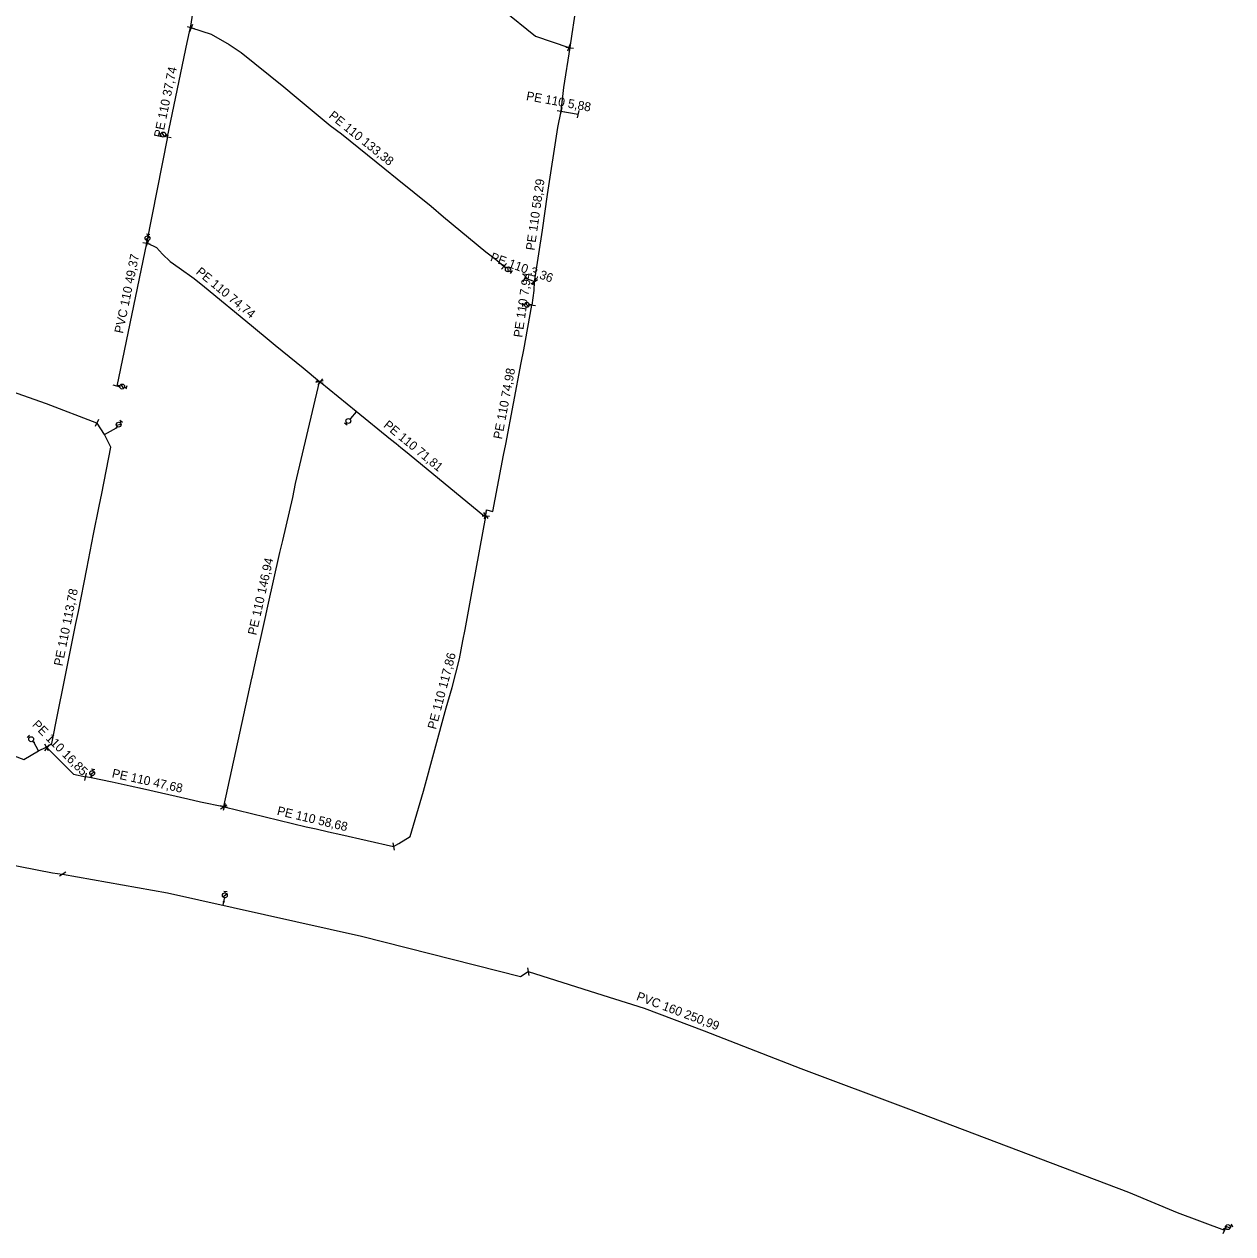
# Model space of a CAD drawing. Extents: x -736619 to -735426, y -1033122 to -1031044.
# Drawn here: x -735849.4 to -735441, y -1033122.5 to -1032713.9 of the extents above; entities that cross this region are included whole.
import ezdxf

# ---------------------------------------------------------------- set-up
doc = ezdxf.new("R2010")
doc.units = 0
for name, color, linetype in [('Vrstva 1', 7, 'Continuous'), ('Vrstva 17', 7, 'Continuous'), ('Vrstva 25', 7, 'Continuous'), ('Vrstva 29', 7, 'Continuous'), ('Vrstva 63', 7, 'Continuous')]:
    doc.layers.add(name, color=color, linetype=linetype)

# ---------------------------------------------------------------- blocks, each defined once
blk = doc.blocks.new('100')
at = {"layer": 'Vrstva 1'}
blk.add_circle((0, 0), 0.127, dxfattribs=at)
blk = doc.blocks.new('132')
at = {"layer": 'Vrstva 1'}
for p, q in [((0.3, 0), (0, 0)), ((1.96, 0), (2.52, 0)), ((2.52, 0.58), (2.52, -0.58))]:
    blk.add_line(p, q, dxfattribs=at)
blk.add_circle((1.13, -0.006), 0.825, dxfattribs=at)
blk = doc.blocks.new('133')
at = {"layer": 'Vrstva 1'}
for p, q in [((0.28, 0), (0, 0)), ((0.54, 0.58), (1.7, -0.58)), ((1.94, 0), (2.52, 0)), ((2.52, 0.58), (2.52, -0.58))]:
    blk.add_line(p, q, dxfattribs=at)
blk.add_circle((1.105, 0.003), 0.825, dxfattribs=at)
blk = doc.blocks.new('147')
at = {"layer": 'Vrstva 1'}
blk.add_line((0, 1.27), (0, -1.27), dxfattribs=at)

msp = doc.modelspace()

# ---------------------------------------------------------------- linework, layer by layer
at = {"layer": 'Vrstva 17'}
for p, q in [((-735793.16, -1032715.071), (-735792.92, -1032715.17)), ((-735665.374, -1032721.804), (-735665.086, -1032721.865)), ((-735668.05, -1032743.33), (-735668.033, -1032743.333)), ((-735668.033, -1032743.333), (-735662.25, -1032744.378)), ((-735800.972, -1032751.994), (-735808.032, -1032787.871)), ((-735808.032, -1032787.871), (-735818.081, -1032836.207)), ((-735808.032, -1032787.871), (-735807.788, -1032787.927)), ((-735677.076, -1032800.904), (-735680.237, -1032799.765)), ((-735677.076, -1032800.904), (-735677.06, -1032800.91)), ((-735749.676, -1032834.78), (-735749.586, -1032834.575)), ((-735749.586, -1032834.575), (-735749.381, -1032834.741)), ((-735693.636, -1032879.879), (-735693.477, -1032879.903)), ((-735693.441, -1032880.18), (-735693.477, -1032879.903)), ((-735841.934, -1032958.161), (-735841.648, -1032958.313)), ((-735782.01, -1032978.282), (-735781.965, -1032978.117)), ((-735782.01, -1032978.282), (-735781.806, -1032978.336))]:
    msp.add_line(p, q, dxfattribs=at)
for points in [[(-735777.177, -1032638.243), (-735776.15, -1032638.619), (-735765.929, -1032646.722), (-735750.433, -1032659.11), (-735744.477, -1032663.984), (-735740.953, -1032666.674), (-735738.072, -1032668.896), (-735725.278, -1032679.218), (-735712.204, -1032689.594), (-735699.686, -1032699.643), (-735687.834, -1032709.024), (-735676.655, -1032717.935), (-735665.374, -1032721.804)], [(-735656.42, -1032671.87), (-735657.93, -1032678.61), (-735660.8, -1032695.69), (-735662.83, -1032706.9), (-735664.36, -1032717.25), (-735665.086, -1032721.865)], [(-735793.16, -1032715.071), (-735793.16, -1032715.07), (-735793.12, -1032714.59), (-735792.19, -1032708.765)], [(-735800.972, -1032751.994), (-735794.359, -1032720.1), (-735793.29, -1032715.52), (-735793.16, -1032715.071)], [(-735792.92, -1032715.17), (-735786.23, -1032717.36), (-735780.12, -1032720.84), (-735776.145, -1032723.548), (-735761.7, -1032735.05), (-735757.495, -1032738.539), (-735746, -1032748.12), (-735742.15, -1032751.03), (-735727.58, -1032762.76), (-735723.37, -1032766.13), (-735711.89, -1032775.45), (-735707.77, -1032779.06), (-735693.41, -1032790.81), (-735689.67, -1032793.7), (-735687.28, -1032795.738)], [(-735665.086, -1032721.865), (-735667.2, -1032735.31), (-735668.05, -1032743.33)], [(-735668.05, -1032743.33), (-735669.19, -1032748.84), (-735672.65, -1032771.42), (-735674.37, -1032783.51), (-735677.06, -1032800.91)], [(-735807.788, -1032787.927), (-735804.739, -1032789.421), (-735802.676, -1032791.633), (-735800.054, -1032794.15), (-735797.096, -1032796.2), (-735791.975, -1032799.883), (-735788.457, -1032802.704), (-735772.647, -1032815.757), (-735765.926, -1032821.267), (-735764.557, -1032822.348), (-735755.129, -1032830.024), (-735749.586, -1032834.575)], [(-735677.06, -1032800.91), (-735677.18, -1032803.86), (-735677.892, -1032808.796)], [(-735693.477, -1032879.903), (-735693.149, -1032878.028), (-735691.073, -1032878.503), (-735687.427, -1032859.529), (-735686.668, -1032855.843), (-735681.476, -1032828.344), (-735680.629, -1032823.961), (-735677.892, -1032808.796)], [(-735824.887, -1032848.661), (-735841.901, -1032842.172), (-735865.619, -1032833.808), (-735896.141, -1032823.373), (-735900.799, -1032826.89)], [(-735781.965, -1032978.117), (-735772.496, -1032934.847), (-735772.429, -1032934.535), (-735771.516, -1032930.278), (-735767.936, -1032914.666), (-735767.113, -1032910.517), (-735763.051, -1032892.437), (-735762.024, -1032888.313), (-735758.634, -1032873.856), (-735757.704, -1032869.109), (-735749.676, -1032834.78)], [(-735749.381, -1032834.741), (-735737.215, -1032844.63), (-735725.686, -1032854.053), (-735723.761, -1032855.595), (-735722.14, -1032856.875), (-735720.533, -1032858.186), (-735694.46, -1032879.666), (-735693.636, -1032879.879)], [(-735841.934, -1032958.161), (-735840.1, -1032956.876), (-735838.067, -1032946.628), (-735836.055, -1032936.593), (-735831.929, -1032916.419), (-735831.093, -1032912.296), (-735828.295, -1032897.901), (-735826.003, -1032886.217), (-735824.038, -1032876.684), (-735823.158, -1032872.506), (-735820.118, -1032856.775), (-735822.241, -1032852.565), (-735824.718, -1032848.725), (-735824.887, -1032848.661)], [(-735724.666, -1032991.664), (-735722.802, -1032990.702), (-735718.951, -1032988.357), (-735714.447, -1032973.042), (-735706.783, -1032944.892), (-735704.851, -1032938.013), (-735702.27, -1032928.245), (-735701.148, -1032922.207), (-735700.425, -1032918.388), (-735697.691, -1032903.526), (-735693.441, -1032880.18)], [(-735923.085, -1032935.961), (-735912.553, -1032939.774), (-735901.778, -1032943.523), (-735897.73, -1032945.001), (-735896.257, -1032945.501), (-735891.938, -1032946.964), (-735877.445, -1032952.202), (-735862.92, -1032957.268), (-735859.475, -1032958.573), (-735849.559, -1032962.291), (-735844.541, -1032959.401), (-735844.539, -1032959.4), (-735841.934, -1032958.161)], [(-735841.648, -1032958.313), (-735832.752, -1032967.228), (-735828.59, -1032968.109)], [(-735782.01, -1032978.282), (-735789.851, -1032976.659), (-735794.066, -1032975.664), (-735809.466, -1032972.252), (-735813.579, -1032971.309), (-735819.663, -1032969.977), (-735826.807, -1032968.487), (-735828.59, -1032968.109)], [(-735781.806, -1032978.336), (-735754.1, -1032985.043), (-735750.797, -1032985.761), (-735746.546, -1032986.767), (-735742.36, -1032987.625), (-735724.666, -1032991.664)], [(-735906.132, -1032981.597), (-735904.521, -1032985.822), (-735885.141, -1032991.258), (-735862.403, -1032996.233), (-735839.791, -1033000.528), (-735836.438, -1033001.046)], [(-735836.438, -1033001.046), (-735800.938, -1033007.38), (-735735.466, -1033021.945), (-735681.684, -1033035.546), (-735679.083, -1033033.941)], [(-735679.083, -1033033.941), (-735656.08, -1033041.23), (-735639.92, -1033046.23), (-735619.6, -1033053.89), (-735586.99, -1033066.65), (-735550.66, -1033080.29), (-735476.24, -1033108.43), (-735459.78, -1033115.28), (-735443.87, -1033121.31)]]:
    msp.add_lwpolyline(points, dxfattribs=at)
at = {"layer": 'Vrstva 63'}
msp.add_line((-735808.032, -1032787.871), (-735807.937, -1032787.334), dxfattribs=at)
for points in [[(-735800.87, -1032751.504), (-735800.966, -1032751.48), (-735801.32, -1032751.43)], [(-735687.28, -1032795.738), (-735687.09, -1032795.9), (-735686.84, -1032796.09)], [(-735677.892, -1032808.796), (-735678.115, -1032808.761), (-735678.434, -1032808.754)], [(-735818.022, -1032835.921), (-735817.606, -1032836.024), (-735817.367, -1032836.076)], [(-735737.215, -1032844.63), (-735737.291, -1032844.833), (-735739.143, -1032847.09)], [(-735822.241, -1032852.565), (-735818.251, -1032850.27), (-735818.136, -1032850.113)], [(-735844.539, -1032959.4), (-735846.15, -1032956.484), (-735846.316, -1032956.298)], [(-735826.807, -1032968.487), (-735826.743, -1032968.219), (-735826.691, -1032968.005)], [(-735782.209, -1033011.546), (-735781.918, -1033010.349), (-735781.776, -1033009.289)], [(-735443.869, -1033121.31), (-735443.92, -1033120.81), (-735443.72, -1033120.73)]]:
    msp.add_lwpolyline(points, dxfattribs=at)

# ---------------------------------------------------------------- block references
at = {"layer": 'Vrstva 25'}
for name, p, xscale, yscale, rotation in [('133', (-735801.32, -1032751.43), 1.0092050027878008, 1.0092050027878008, 168.88308178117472), ('133', (-735807.937, -1032787.334), 0.9999999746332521, 0.9999999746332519, 80.00000055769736), ('133', (-735686.84, -1032796.09), 0.9999999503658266, 0.9999999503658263, -37.999999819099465), ('133', (-735678.434, -1032808.754), 0.9999999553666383, 0.9999999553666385, 178.99999999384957), ('133', (-735817.367, -1032836.076), 1.0028916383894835, 1.0028916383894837, -13.697207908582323), ('133', (-735818.136, -1032850.113), 0.9999999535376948, 0.9999999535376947, 53.99999865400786), ('132', (-735739.143, -1032847.09), 0.9999999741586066, 0.9999999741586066, -129.99999870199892), ('132', (-735846.316, -1032956.298), 0.9999999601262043, 0.9999999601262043, 131.99999877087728), ('133', (-735826.691, -1032968.005), 0.9999999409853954, 0.9999999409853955, 75.99999967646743), ('133', (-735781.776, -1033009.289), 0.9999999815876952, 0.9999999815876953, 82.0000004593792), ('133', (-735443.72, -1033120.73), 1.025136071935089, 1.0251360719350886, 25.250758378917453)]:
    msp.add_blockref(name, p, dxfattribs=dict(at, xscale=xscale, yscale=yscale, rotation=rotation))
at = {"layer": 'Vrstva 29'}
for p, xscale, yscale, rotation in [((-735793.16, -1032715.071), 0.9999999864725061, 0.9999999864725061, 74.0000013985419), ((-735792.92, -1032715.17), 1.0296949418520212, 1.0296949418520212, 155.86621099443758), ((-735665.374, -1032721.804), 1.0365458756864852, 1.0365458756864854, -21.97149085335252), ((-735665.086, -1032721.865), 0.9999999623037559, 0.999999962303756, 80.99999986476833), ((-735668.05, -1032743.33), 0.9999999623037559, 0.999999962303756, 80.99999986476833), ((-735668.033, -1032743.333), 1.0060666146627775, 1.0060666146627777, -12.654735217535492), ((-735662.25, -1032744.378), 1.0060666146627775, 1.0060666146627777, -12.654735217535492), ((-735800.972, -1032751.994), 0.9999999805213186, 0.9999999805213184, 79.00000058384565), ((-735808.032, -1032787.871), 0.9999999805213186, 0.9999999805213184, 79.00000058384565), ((-735807.788, -1032787.927), 1.0275072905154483, 1.027507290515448, -24.689105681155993), ((-735687.28, -1032795.738), 0.9999999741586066, 0.9999999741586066, 140.00000129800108), ((-735680.237, -1032799.765), 1.0296949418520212, 1.0296949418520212, 155.86621099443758), ((-735677.06, -1032800.91), 0.9999999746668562, 0.999999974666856, 124.00000045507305), ((-735677.076, -1032800.904), 1.0275072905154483, 1.027507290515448, -24.689105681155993), ((-735677.892, -1032808.796), 0.9999999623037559, 0.999999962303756, 80.99999986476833), ((-735749.676, -1032834.78), 0.9999999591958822, 0.9999999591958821, 72.00000054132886), ((-735749.586, -1032834.575), 0.9999999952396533, 0.9999999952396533, 102.9999994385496), ((-735749.381, -1032834.741), 0.9999999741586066, 0.9999999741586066, -39.999998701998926), ((-735818.081, -1032836.207), 0.9999999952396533, 0.9999999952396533, -102.9999994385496), ((-735824.887, -1032848.661), 1.025136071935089, 1.0251360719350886, -25.250758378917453), ((-735693.441, -1032880.18), 0.9999999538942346, 0.9999999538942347, -92.0000000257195), ((-735693.477, -1032879.903), 0.9999999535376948, 0.9999999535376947, 36.000001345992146), ((-735693.636, -1032879.879), 1.0028916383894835, 1.0028916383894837, -13.697207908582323), ((-735841.934, -1032958.161), 0.9999999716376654, 0.9999999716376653, 29.999998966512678), ((-735841.648, -1032958.313), 0.9999999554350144, 0.9999999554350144, 143.00000079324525), ((-735828.59, -1032968.109), 1.0045862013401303, 1.00458620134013, 166.82590933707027), ((-735781.965, -1032978.117), 0.9999999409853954, 0.9999999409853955, 75.99999967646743), ((-735782.01, -1032978.282), 0.9999999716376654, 0.9999999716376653, 119.99999896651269), ((-735781.806, -1032978.336), 0.999999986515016, 0.9999999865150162, -15.000000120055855), ((-735724.666, -1032991.664), 1.0098116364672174, 1.0098116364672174, 10.610300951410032), ((-735836.438, -1033001.046), 0.9999999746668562, 0.999999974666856, -55.999999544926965), ((-735679.083, -1033033.941), 1.0098116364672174, 1.0098116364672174, 10.610300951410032), ((-735443.87, -1033121.31), 1.0275072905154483, 1.027507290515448, -24.689105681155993)]:
    msp.add_blockref('147', p, dxfattribs=dict(at, xscale=xscale, yscale=yscale, rotation=rotation))
at = {"layer": 'Vrstva 63'}
for p, xscale, yscale, rotation in [((-735800.966, -1032751.48), 1.0045862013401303, 1.00458620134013, -13.17409066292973), ((-735687.09, -1032795.9), 0.9999999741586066, 0.9999999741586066, -39.999998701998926), ((-735678.115, -1032808.761), 1.0011216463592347, 1.0011216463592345, -6.5826102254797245), ((-735817.606, -1032836.024), 1.0009847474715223, 1.0009847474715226, -14.22432628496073), ((-735737.291, -1032844.833), 0.9999999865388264, 0.9999999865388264, 59.99999955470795), ((-735818.251, -1032850.27), 0.9999999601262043, 0.9999999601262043, 41.999998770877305), ((-735846.15, -1032956.484), 0.9999999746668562, 0.999999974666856, -55.999999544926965), ((-735826.743, -1032968.219), 0.9999999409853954, 0.9999999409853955, 75.99999967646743), ((-735781.918, -1033010.349), 0.9999999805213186, 0.9999999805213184, 79.00000058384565), ((-735443.92, -1033120.81), 0.9999999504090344, 0.9999999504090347, 58.99999841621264)]:
    msp.add_blockref('100', p, dxfattribs=dict(at, xscale=xscale, yscale=yscale, rotation=rotation))

# ---------------------------------------------------------------- texts
for s, rotation, p in [('PE 110 37,74', 78.29, (-735802.707, -1032752.489)), ('PE 110 5,88', 349.76, (-735679.937, -1032739.556)), ('PE 110 133,38', 321.16, (-735746.731, -1032745.286)), ('PE 110 58,29', 81.9, (-735676.979, -1032790.489)), ('PVC 110 49,37', 78.26, (-735816.046, -1032818.562)), ('PE 110 3,36', 340.18, (-735692.134, -1032793.776)), ('PE 110 74,74', 320.46, (-735791.595, -1032798.039)), ('PE 110 7,94', 81.79, (-735681.124, -1032819.9)), ('PE 110 74,98', 79.31, (-735688, -1032854.281)), ('PE 110 71,81', 320.52, (-735728.216, -1032849.783)), ('PE 110 146,94', 77.34, (-735770.992, -1032920.488)), ('PE 110 113,78', 78.54, (-735836.499, -1032930.913)), ('PE 110 117,86', 75.2, (-735710.285, -1032952.317)), ('PE 110 16,85', 314.94, (-735846.904, -1032950.78)), ('PE 110 47,68', 347.51, (-735819.95, -1032968.29)), ('PE 110 58,68', 346.69, (-735764.174, -1032980.952)), ('PVC 160 250,99', 339.35, (-735642.777, -1033043.444))]:
    msp.add_text(s, height=2.99999, rotation=rotation, dxfattribs=at).set_placement(p)

doc.saveas('drawing.dxf')
